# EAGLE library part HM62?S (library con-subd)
SUB-D
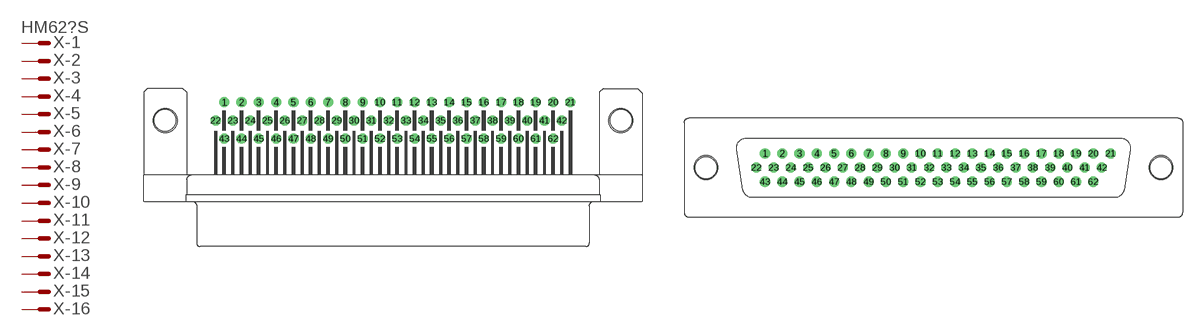
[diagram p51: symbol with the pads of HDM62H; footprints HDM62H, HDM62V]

Designator prefix X; gates -1=MV -2=M -3=M -4=M -5=M -6=M -7=M -8=M -9=M -10=M -11=M -12=M -13=M -14=M -15=M -16=M -17=M -18=M -19=M -20=M -21=M -22=M -23=M -24=M -25=M -26=M -27=M -28=M -29=M -30=M -31=M -32=M -33=M -34=M -35=M -36=M -37=M -38=M -39=M -40=M -41=M -42=M -43=M -44=M -45=M -46=M -47=M -48=M -49=M -50=M -51=M -52=M -53=M -54=M -55=M -56=M -57=M -58=M -59=M -60=M -61=M -62=M

## HM62HS (OC_FARNELL: unknown; OC_NEWARK: unknown)  [HDM62H]
1  -1:M  pas
2  -2:M  pas
3  -3:M  pas
4  -4:M  pas
5  -5:M  pas
6  -6:M  pas
7  -7:M  pas
8  -8:M  pas
9  -9:M  pas
10  -10:M  pas
11  -11:M  pas
12  -12:M  pas
13  -13:M  pas
14  -14:M  pas
15  -15:M  pas
16  -16:M  pas
17  -17:M  pas
18  -18:M  pas
19  -19:M  pas
20  -20:M  pas
21  -21:M  pas
22  -22:M  pas
23  -23:M  pas
24  -24:M  pas
25  -25:M  pas
26  -26:M  pas
27  -27:M  pas
28  -28:M  pas
29  -29:M  pas
30  -30:M  pas
31  -31:M  pas
32  -32:M  pas
33  -33:M  pas
34  -34:M  pas
35  -35:M  pas
36  -36:M  pas
37  -37:M  pas
38  -38:M  pas
39  -39:M  pas
40  -40:M  pas
41  -41:M  pas
42  -42:M  pas
43  -43:M  pas
44  -44:M  pas
45  -45:M  pas
46  -46:M  pas
47  -47:M  pas
48  -48:M  pas
49  -49:M  pas
50  -50:M  pas
51  -51:M  pas
52  -52:M  pas
53  -53:M  pas
54  -54:M  pas
55  -55:M  pas
56  -56:M  pas
57  -57:M  pas
58  -58:M  pas
59  -59:M  pas
60  -60:M  pas
61  -61:M  pas
62  -62:M  pas

## HM62VS (OC_FARNELL: unknown; OC_NEWARK: unknown)  [HDM62V]
Pads as for HDM62H

## Footprint HDM62H (pad centres in mm)
SUB-D
drill 0.9 round: 1 -23.527,2.54; 2 -21.114,2.54; 3 -18.701,2.54; 4 -16.288,2.54; 5 -13.875,2.54; 6 -11.462,2.54; 7 -9.049,2.54; 8 -6.636,2.54; 9 -4.223,2.54; 10 -1.81,2.54; 11 0.603,2.54; 12 3.016,2.54; 13 5.429,2.54; 14 7.842,2.54; 15 10.255,2.54; 16 12.668,2.54; 17 15.081,2.54; 18 17.494,2.54; 19 19.907,2.54; 20 22.32,2.54; 21 24.733,2.54; 22 -24.734,0; 23 -22.321,0; 24 -19.908,0; 25 -17.495,0; 26 -15.082,0; 27 -12.669,0; 28 -10.256,0; 29 -7.843,0; 30 -5.43,0; 31 -3.017,0; 32 -0.604,0; 33 1.809,0; 34 4.222,0; 35 6.635,0; 36 9.048,0; 37 11.461,0; 38 13.874,0; 39 16.287,0; 40 18.7,0; 41 21.113,0; 42 23.526,0; 43 -23.527,-2.54; 44 -21.114,-2.54; 45 -18.701,-2.54; 46 -16.288,-2.54; 47 -13.875,-2.54; 48 -11.462,-2.54; 49 -9.049,-2.54; 50 -6.636,-2.54; 51 -4.223,-2.54; 52 -1.81,-2.54; 53 0.603,-2.54; 54 3.016,-2.54; 55 5.429,-2.54; 56 7.842,-2.54; 57 10.255,-2.54; 58 12.668,-2.54; 59 15.081,-2.54; 60 17.494,-2.54; 61 19.907,-2.54; 62 22.32,-2.54
hole 3 at -31.75,0
hole 3 at 31.75,0

## Footprint HDM62V (pad centres in mm)
SUB-D
drill 0.9 round: 1 -23.532,1.98; 2 -21.119,1.98; 3 -18.706,1.98; 4 -16.293,1.98; 5 -13.88,1.98; 6 -11.467,1.98; 7 -9.054,1.98; 8 -6.641,1.98; 9 -4.228,1.98; 10 -1.815,1.98; 11 0.598,1.98; 12 3.011,1.98; 13 5.424,1.98; 14 7.837,1.98; 15 10.25,1.98; 16 12.663,1.98; 17 15.076,1.98; 18 17.489,1.98; 19 19.902,1.98; 20 22.315,1.98; 21 24.728,1.98; 22 -24.739,0; 23 -22.325,0; 24 -19.912,0; 25 -17.499,0; 26 -15.086,0; 27 -12.673,0; 28 -10.26,0; 29 -7.847,0; 30 -5.434,0; 31 -3.021,0; 32 -0.608,0; 33 1.805,0; 34 4.218,0; 35 6.631,0; 36 9.044,0; 37 11.457,0; 38 13.87,0; 39 16.283,0; 40 18.696,0; 41 21.109,0; 42 23.522,0; 43 -23.532,-1.98; 44 -21.119,-1.98; 45 -18.706,-1.98; 46 -16.293,-1.98; 47 -13.88,-1.98; 48 -11.467,-1.98; 49 -9.054,-1.98; 50 -6.641,-1.98; 51 -4.228,-1.98; 52 -1.815,-1.98; 53 0.598,-1.98; 54 3.011,-1.98; 55 5.424,-1.98; 56 7.837,-1.98; 57 10.25,-1.98; 58 12.663,-1.98; 59 15.076,-1.98; 60 17.489,-1.98; 61 19.902,-1.98; 62 22.315,-1.98
hole 3 at -31.75,0
hole 3 at 31.75,0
